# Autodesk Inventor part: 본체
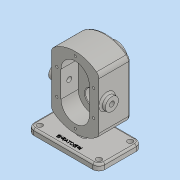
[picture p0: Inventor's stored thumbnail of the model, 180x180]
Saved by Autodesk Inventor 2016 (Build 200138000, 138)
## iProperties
Created: 2019-03
Part Number: 본체
Material: 일반
Document SubType Name: Modeling
Designer: MIRAE
Density: 1 g/cm^3
Appearance: 기본값
Mass: 439.69 g
Surface Area: 719.273 cm^2
Volume: 439.69 cm^3
Author: MIRAE
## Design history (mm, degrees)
sketch "스케치1"
  geometry: L1 (-40, -60)-(0, -60); L2 (40, -60)-(40, -44.721); L3 (40, 60)-(0, 60); L4 (-40, 60)-(-40, 44.721); L5 (-40, -60)-(40, 60); L6 (40, -60)-(-40, 60); L7 (-40, 44.721)-(-40, -44.721); L8 (0, 60)-(-40, 60); L9 (40, 44.721)-(40, 60); L10 (40, -44.721)-(40, 44.721); L11 (0, -60)-(40, -60); L12 (-40, -44.721)-(-40, -60); A1 r 60 centre (0, 0) between (-40, -44.721) and (40, -44.721); A2 r 60 centre (0, 0) between (40, 44.721) and (-40, 44.721); 1 further point
  constraints: 24 end point, 13 parallel, 9 point on circle, 6 perpendicular, 2 centre point, 2 horizontal, 2 midpoint, 1 coincident
  dimensions: "d0" = 80 distance of L4.start L3.start; "d1" = 120 distance of L3.start L2.start; "d13" = 120 diameter of A1
extrude "돌출1" new body sketch "스케치1" distance "d2" = 53; taper "d3" = 0 deg
node "작업 평면2"
sketch "스케치4"
  geometry: L1 (40, 53)-(-40, 53) reference; L2 (-60, 53)-(60, 53); L3 (60, 53)-(60, -20); L4 (60, -20)-(-60, -20); L5 (-60, -20)-(-60, 53); 2 further points
  constraints: 8 end point, 2 midpoint, 2 parallel, 1 horizontal, 1 perpendicular
  dimensions: "d15" = 120 distance of L3.end L4.end; "d16" = 73 distance of L2.end L3.end
extrude "돌출4" join sketch "스케치4" distance "d17" = 10; taper "d18" = 0 deg
sketch "스케치5"
  geometry: L1 (-6, 53)-(6, 53); L2 (6, 53)-(6, 10); L3 (6, 10)-(-6, 10); L4 (-6, 10)-(-6, 53); L5 (-60, 53)-(60, 53) reference; 2 further points
  constraints: 8 end point, 2 midpoint, 2 parallel, 1 horizontal, 1 perpendicular
  dimensions: "d21" = 12 distance of L2.end L3.end; "d22" = 43 distance of L1.end L2.end
extrude "돌출5" join sketch "스케치5" stored distance "d23" = 10; taper "d24" = 0 deg
sketch "스케치6"
  geometry: L1 (0, 0)-(0, -22); C1 r 19 at (0, -22)
  constraints: 2 end point, 1 centre point, 1 coincident, 1 vertical
  dimensions: "d25" = 22 distance of L1.start L1.end; "d26" = 38 diameter of C1
extrude "돌출6" join sketch "스케치6" distance "d27" = 17; taper "d28" = 0 deg
sketch "스케치7"
  geometry: L1 (0, 0)-(89.443, 0) reference; C1 r 11 at (44.721, 14); 2 further points
  constraints: 1 centre point, 1 midpoint, 1 vertical alignment
  dimensions: "d29" = 22 diameter of C1; "d30" = 14 distance of point (44.721, 0) C1.centre
extrude "돌출7" join sketch "스케치7" distance "d31" = 8; taper "d32" = 0 deg
sketch "스케치9"
  geometry: L1 (0, -22)-(0, 22); L2 (24, -22)-(24, 22); L3 (-24, 22)-(-24, -22); A1 r 24 centre (0, -22) between (-24, -22) and (24, -22); A2 r 24 centre (0, 22) between (24, 22) and (-24, 22); 1 further point
  constraints: 8 end point, 4 point on circle, 4 tangent, 2 centre point, 1 midpoint, 1 parallel, 1 vertical
  dimensions: "d42" = 48 diameter of A2; "d43" = 22 distance of point (0, 0) L1.end
extrude "돌출8" cut sketch "스케치9" distance "d44" = 29; taper "d45" = 0 deg
hole "구멍1" diameter "d35" = 8.376; stored, may be unused: countersink angle "d39" = 90 deg, drill point angle "d41" = 118 deg; dims "d36" = 20, "d37" = 4, "d38" = 2, "d40" = 30, "d46" = 10, "d47" = 10
sketch "스케치10"
  geometry: L1 (0, 0)-(0, -22); C1 r 12.5 at (0, -22)
  constraints: 2 end point, 1 centre point, 1 coincident, 1 vertical
  dimensions: "d48" = 22 distance of L1.start L1.end; "d49" = 25 diameter of C1
extrude "돌출9" cut sketch "스케치10" distance "d50" = 15; taper "d51" = 0 deg
sketch "스케치11"
  geometry: L1 (0, 0)-(0, 22); C1 r 12.5 at (0, 22)
  constraints: 2 end point, 1 centre point, 1 coincident, 1 vertical
  dimensions: "d52" = 22 distance of L1.start L1.end; "d53" = 25 diameter of C1
extrude "돌출10" cut sketch "스케치11" distance "d54" = 15; taper "d55" = 0 deg
sketch "스케치12"
  geometry: C1 r 12.5 at (0, 0) reference; C2 r 8.5 at (0, 0); 1 further point
  constraints: 1 centre point, 1 coincident
  dimensions: "d56" = 17 diameter of C2
extrude "돌출11" cut sketch "스케치12" stored distance "d57" = 15; taper "d58" = 0 deg
sketch "스케치13"
  geometry: C1 r 8.5 at (0, 0) reference; C2 r 14 at (0, 0); 1 further point
  constraints: 1 centre point, 1 coincident
  dimensions: "d59" = 28 diameter of C2
extrude "돌출12" cut sketch "스케치13" distance "d60" = 7.3; taper "d61" = 0 deg
fillet "모깎기1" dims "d62" = 10
sketch "스케치14"
  geometry: A1 r 10 centre (-50, -10) between (-60, -10) and (-50, -20) reference; A2 r 10 centre (-50, 43) between (-50, 53) and (-60, 43) reference; A3 r 10 centre (50, -10) between (50, -20) and (60, -10) reference; A4 r 10 centre (50, 43) between (60, 43) and (50, 53) reference; 5 further points
  constraints: 4 coincident
hole "구멍2" sketch "스케치14" at (-50, -10), (-50, 43), (50, -10), (50, 43) diameter "d63" = 9; stored, may be unused: countersink angle "d67" = 90 deg, drill point angle "d69" = 118 deg; dims "d64" = 20, "d65" = 4, "d66" = 2, "d68" = 30
sketch "스케치15"
  geometry: L1 (-31, 22)-(31, 22); C1 r 8.5 at (0, 22) reference; A1 r 31 centre (0, 22) between (-31, 22) and (31, 22); 5 further points
  constraints: 4 coincident, 3 point on circle, 2 end point, 1 centre point, 1 horizontal, 1 horizontal alignment, 1 midpoint, 1 vertical alignment
  dimensions: "d70" = 62 diameter of A1
hole "구멍3" sketch "스케치15" at (-31, 22), (31, 22), (0, 53) diameter "d72" = 4.134; stored, may be unused: countersink angle "d76" = 90 deg, drill point angle "d78" = 118 deg; dims "d73" = 10, "d74" = 4, "d75" = 2, "d77" = 12
fillet "모깎기2" dims "d79" = 3
fillet "모깎기3" dims "d80" = 3
sketch "스케치16"
  geometry: L1 (-50, -20)-(50, -20) reference; L2 (-60, 43)-(-60, -10) reference; 2 further points
  constraints: 1 other
  dimensions: "d81" = 10 distance from line of L1 point (0, -10); "d82" = 60 distance from line of L2 point (0, -10)
extrude "돌출13" join sketch "스케치16" distance "d83" = 0.5; taper "d84" = 0 deg
chamfer "모따기1" distance "d85" = 1; stored, may be unused: second distance "d86" = 2, angle "d87" = 45 deg
fillet "모깎기4" dims "d88" = 0.5
chamfer "모따기2" distance "d89" = 0.7; stored, may be unused: second distance "d90" = 2, angle "d91" = 30 deg
sketch "스케치17"
  geometry: L1 (50, 157.843)-(127.024, 157.843); L2 (127.024, 157.843)-(127.024, -10.558); L3 (127.024, -10.558)-(50, -10.558); L4 (50, -10.558)-(50, 157.843); 1 further point
  constraints: 8 end point, 2 parallel, 1 horizontal, 1 perpendicular
extrude "돌출14" cut sketch "스케치17" stored distance "d92" = 10; taper "d93" = 0 deg
node "솔리드1"
mirror "대칭1"
mirror "대칭2"
other parameters: "d14" = -78
